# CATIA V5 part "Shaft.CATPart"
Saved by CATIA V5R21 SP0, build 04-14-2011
Part number: Shaft
Bounding box of the stored display mesh (mm): x -10.997 to 10.997, y 0 to 134, z -10.875 to 10.875
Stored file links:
  D:\CATIA V5R21 E-RESOURCES\CATIA-V5R21\catia-v5r21-Prts\c12_catia_v5r21_prt\c12_catia_v5r21figr_12-53\Shaft.CATPart
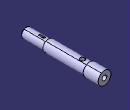
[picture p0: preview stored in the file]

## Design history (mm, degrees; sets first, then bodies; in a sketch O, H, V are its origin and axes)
Body1 (main body)
  Sketch1 on yz-plane, origin (0, 0, 0), H (0, 1, 0), V (0, 0, 1)
    line L1 (0, 0) -> (0, 8)
    line L2 (0, 8) -> (39, 8)
    line L3 (39, 8) -> (39, 9.5)
    line L4 (39, 9.5) -> (109, 9.5)
    line L5 (109, 9.5) -> (109, 11)
    line L6 (109, 11) -> (134, 11)
    line L7 (134, 11) -> (134, 0)
    point P7 (134, 0)
    line L8 (134, 0) -> (0, 0)
    length L1 = 8
    length L8 = 134
    length L7 = 11
    distance L4 L8 = 9.5
    length L6 = 25
    length L4 = 70
    vertical: L1 V, L3 V, L5 V, L7 V
    horizontal: L2 H, L4 H, L6 H, L8 H
    coincidence: P7 H
  Shaft1: profile Sketch1, axis edge of Sketch1, angle 360
  Chamfer1: length 1.5, angle 45, on 1 edge
  Sketch2 on xy-plane, origin (0, 0, 0), H (1, 0, 0), V (0, 1, 0)
    circle A1 centre (0, 97) radius 4.15
    point P1 (0, 97)
    reference projected line E1 (-11, 109) -> (11, 109) from edge of Shaft1
    radius A1 = 4.15
    distance E1 P1 = 12
    coincidence: P1 V
  Pocket1: profile Sketch2, direction (0, 0, -1), length 20, mirrored extent
  Sketch3 on face of Shaft1, origin (0, 134, 0), H (-1, 0, 0), V (0, 0, 1)
    circle A1 centre (0, 0) radius 4.15
    radius A1 = 4.15
  Pocket2: profile Sketch3, direction (0, -1, 0), length 44
  Sketch4 on yz-plane, origin (0, 0, 0), H (0, 1, 0), V (0, 0, 1)
    point P1 (23, 8)
    line L1 (23, 8) -> (33, 8)
    arc A1 centre (28, 12.899) radius 7 from (23, 8) to (33, 8) ccw
    reference projected line E1 (39, -9.5) -> (39, 9.5) from edge of Shaft1
    length L1 = 10
    distance L1 H = 8
    distance P1 E1 = 16
    radius A1 = 7
    horizontal: L1 H
  Pocket3: profile Sketch4, direction (-1, 0, 0), length 1.6, mirrored extent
